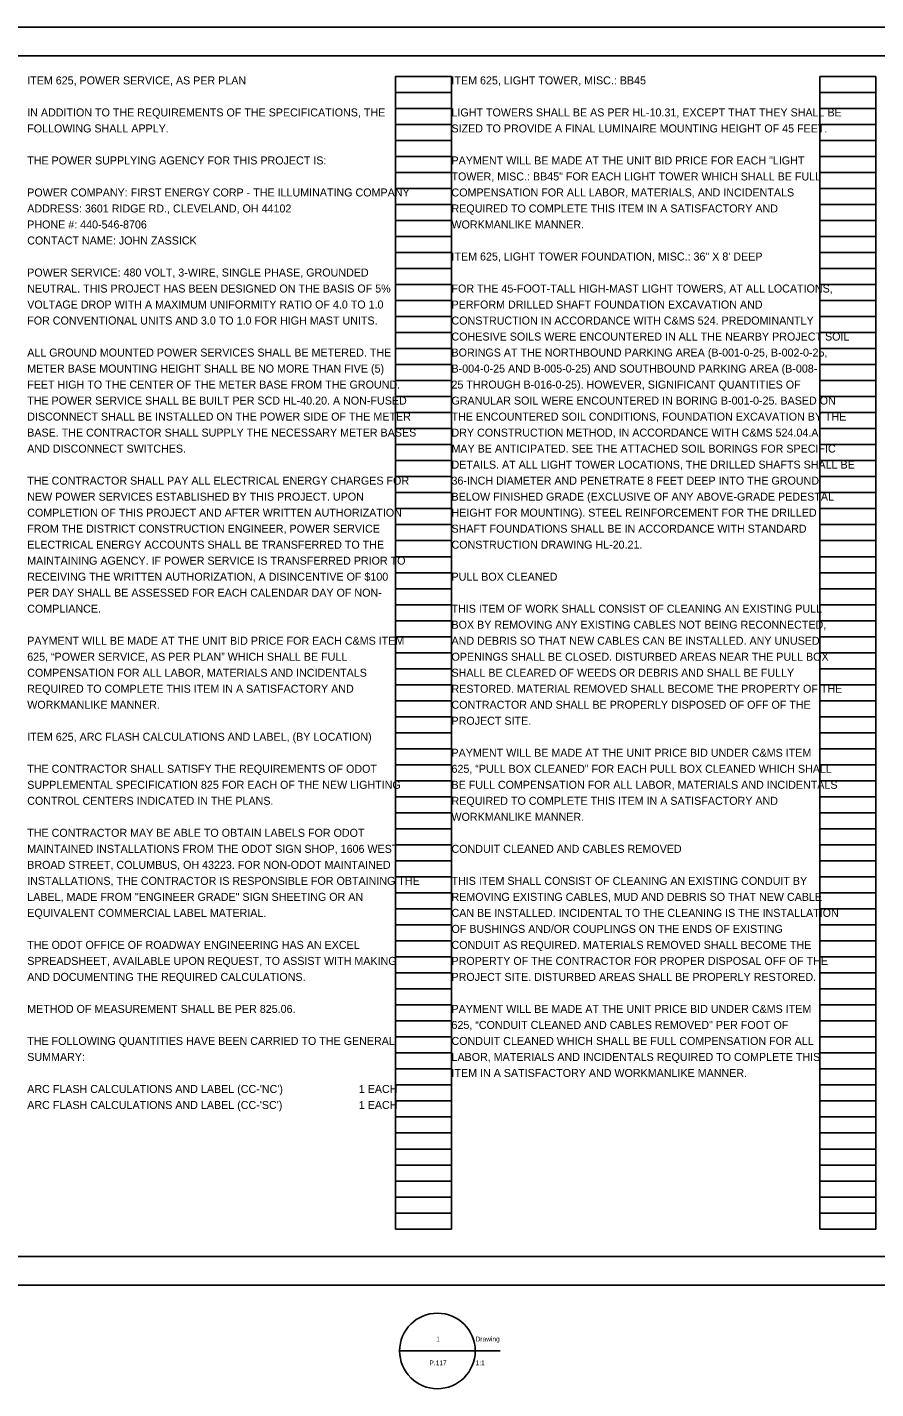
# Model space of a CAD drawing. Extents: x 0 to 49.8, y -1.8 to 22.
# Drawn here: x 9.82 to 24.66, y -1.81 to 22 of the extents above; entities that cross this region are included whole.
import ezdxf

# ---------------------------------------------------------------- set-up
doc = ezdxf.new("R2010")
doc.units = 0
for name, color, linetype in [('SH_Border', 7, 'Continuous'), ('SH_Cut_Line', 7, 'Continuous'), ('SH_Data', 7, 'Continuous'), ('SH_Text', 7, 'Continuous')]:
    doc.layers.add(name, color=color, linetype=linetype)

msp = doc.modelspace()

# ---------------------------------------------------------------- linework, layer by layer
at = {"layer": 'SH_Border'}
msp.add_lwpolyline([(1.5, 21.5), (33.5, 21.5), (33.5, 0.5), (1.5, 0.5)], close=True, dxfattribs=at)
at = {"layer": 'SH_Cut_Line'}
msp.add_lwpolyline([(0, 0), (34, 0), (34, 22), (0, 22)], close=True, dxfattribs=at)
at = {"layer": 'SH_Data'}
for p, q in [((16.26, 0.98), (16.26, 21.14)), ((16.26, 21.14), (17.24, 21.14)), ((17.24, 0.98), (17.24, 21.14)), ((23.68, 0.98), (23.68, 21.14)), ((23.68, 21.14), (24.66, 21.14)), ((24.66, 0.98), (24.66, 21.14)), ((16.26, 20.86), (17.24, 20.86)), ((23.68, 20.86), (24.66, 20.86)), ((16.26, 20.58), (17.24, 20.58)), ((23.68, 20.58), (24.66, 20.58)), ((16.26, 20.3), (17.24, 20.3)), ((23.68, 20.3), (24.66, 20.3)), ((16.26, 20.02), (17.24, 20.02)), ((23.68, 20.02), (24.66, 20.02)), ((16.26, 19.74), (17.24, 19.74)), ((23.68, 19.74), (24.66, 19.74)), ((16.26, 19.46), (17.24, 19.46)), ((23.68, 19.46), (24.66, 19.46)), ((16.26, 19.18), (17.24, 19.18)), ((23.68, 19.18), (24.66, 19.18)), ((16.26, 18.9), (17.24, 18.9)), ((23.68, 18.9), (24.66, 18.9)), ((16.26, 18.62), (17.24, 18.62)), ((23.68, 18.62), (24.66, 18.62)), ((16.26, 18.34), (17.24, 18.34)), ((23.68, 18.34), (24.66, 18.34)), ((16.26, 18.06), (17.24, 18.06)), ((23.68, 18.06), (24.66, 18.06)), ((16.26, 17.78), (17.24, 17.78)), ((23.68, 17.78), (24.66, 17.78)), ((16.26, 17.5), (17.24, 17.5)), ((23.68, 17.5), (24.66, 17.5)), ((16.26, 17.22), (17.24, 17.22)), ((23.68, 17.22), (24.66, 17.22)), ((16.26, 16.94), (17.24, 16.94)), ((23.68, 16.94), (24.66, 16.94)), ((16.26, 16.66), (17.24, 16.66)), ((23.68, 16.66), (24.66, 16.66)), ((16.26, 16.38), (17.24, 16.38)), ((23.68, 16.38), (24.66, 16.38)), ((16.26, 16.1), (17.24, 16.1)), ((23.68, 16.1), (24.66, 16.1)), ((16.26, 15.82), (17.24, 15.82)), ((23.68, 15.82), (24.66, 15.82)), ((16.26, 15.54), (17.24, 15.54)), ((23.68, 15.54), (24.66, 15.54)), ((16.26, 15.26), (17.24, 15.26)), ((23.68, 15.26), (24.66, 15.26)), ((16.26, 14.98), (17.24, 14.98)), ((23.68, 14.98), (24.66, 14.98)), ((16.26, 14.7), (17.24, 14.7)), ((23.68, 14.7), (24.66, 14.7)), ((16.26, 14.42), (17.24, 14.42)), ((23.68, 14.42), (24.66, 14.42)), ((16.26, 14.14), (17.24, 14.14)), ((23.68, 14.14), (24.66, 14.14)), ((16.26, 13.86), (17.24, 13.86)), ((23.68, 13.86), (24.66, 13.86)), ((16.26, 13.58), (17.24, 13.58)), ((23.68, 13.58), (24.66, 13.58)), ((16.26, 13.3), (17.24, 13.3)), ((23.68, 13.3), (24.66, 13.3)), ((16.26, 13.02), (17.24, 13.02)), ((23.68, 13.02), (24.66, 13.02)), ((16.26, 12.74), (17.24, 12.74)), ((23.68, 12.74), (24.66, 12.74)), ((16.26, 12.46), (17.24, 12.46)), ((23.68, 12.46), (24.66, 12.46)), ((16.26, 12.18), (17.24, 12.18)), ((23.68, 12.18), (24.66, 12.18)), ((16.26, 11.9), (17.24, 11.9)), ((23.68, 11.9), (24.66, 11.9)), ((16.26, 11.62), (17.24, 11.62)), ((23.68, 11.62), (24.66, 11.62)), ((16.26, 11.34), (17.24, 11.34)), ((23.68, 11.34), (24.66, 11.34)), ((16.26, 11.06), (17.24, 11.06)), ((23.68, 11.06), (24.66, 11.06)), ((16.26, 10.78), (17.24, 10.78)), ((23.68, 10.78), (24.66, 10.78)), ((16.26, 10.5), (17.24, 10.5)), ((23.68, 10.5), (24.66, 10.5)), ((16.26, 10.22), (17.24, 10.22)), ((23.68, 10.22), (24.66, 10.22)), ((16.26, 9.94), (17.24, 9.94)), ((23.68, 9.94), (24.66, 9.94)), ((16.26, 9.66), (17.24, 9.66)), ((23.68, 9.66), (24.66, 9.66)), ((16.26, 9.38), (17.24, 9.38)), ((23.68, 9.38), (24.66, 9.38)), ((16.26, 9.1), (17.24, 9.1)), ((23.68, 9.1), (24.66, 9.1)), ((16.26, 8.82), (17.24, 8.82)), ((23.68, 8.82), (24.66, 8.82)), ((16.26, 8.54), (17.24, 8.54)), ((23.68, 8.54), (24.66, 8.54)), ((16.26, 8.26), (17.24, 8.26)), ((23.68, 8.26), (24.66, 8.26)), ((16.26, 7.98), (17.24, 7.98)), ((23.68, 7.98), (24.66, 7.98)), ((16.26, 7.7), (17.24, 7.7)), ((23.68, 7.7), (24.66, 7.7)), ((16.26, 7.42), (17.24, 7.42)), ((23.68, 7.42), (24.66, 7.42)), ((16.26, 7.14), (17.24, 7.14)), ((23.68, 7.14), (24.66, 7.14)), ((16.26, 6.86), (17.24, 6.86)), ((23.68, 6.86), (24.66, 6.86)), ((16.26, 6.58), (17.24, 6.58)), ((23.68, 6.58), (24.66, 6.58)), ((16.26, 6.3), (17.24, 6.3)), ((23.68, 6.3), (24.66, 6.3)), ((16.26, 6.02), (17.24, 6.02)), ((23.68, 6.02), (24.66, 6.02)), ((16.26, 5.74), (17.24, 5.74)), ((23.68, 5.74), (24.66, 5.74)), ((16.26, 5.46), (17.24, 5.46)), ((23.68, 5.46), (24.66, 5.46)), ((16.26, 5.18), (17.24, 5.18)), ((23.68, 5.18), (24.66, 5.18)), ((16.26, 4.9), (17.24, 4.9)), ((23.68, 4.9), (24.66, 4.9)), ((16.26, 4.62), (17.24, 4.62)), ((23.68, 4.62), (24.66, 4.62)), ((16.26, 4.34), (17.24, 4.34)), ((23.68, 4.34), (24.66, 4.34)), ((16.26, 4.06), (17.24, 4.06)), ((23.68, 4.06), (24.66, 4.06)), ((16.26, 3.78), (17.24, 3.78)), ((23.68, 3.78), (24.66, 3.78)), ((16.26, 3.5), (17.24, 3.5)), ((23.68, 3.5), (24.66, 3.5)), ((16.26, 3.22), (17.24, 3.22)), ((23.68, 3.22), (24.66, 3.22)), ((16.26, 2.94), (17.24, 2.94)), ((23.68, 2.94), (24.66, 2.94)), ((16.26, 2.66), (17.24, 2.66)), ((23.68, 2.66), (24.66, 2.66)), ((16.26, 2.38), (17.24, 2.38)), ((23.68, 2.38), (24.66, 2.38)), ((16.26, 2.1), (17.24, 2.1)), ((23.68, 2.1), (24.66, 2.1)), ((16.26, 1.82), (17.24, 1.82)), ((23.68, 1.82), (24.66, 1.82)), ((16.26, 1.54), (17.24, 1.54)), ((23.68, 1.54), (24.66, 1.54)), ((16.26, 1.26), (17.24, 1.26)), ((23.68, 1.26), (24.66, 1.26)), ((16.26, 0.98), (17.24, 0.98)), ((23.68, 0.98), (24.66, 0.98))]:
    msp.add_line(p, q, dxfattribs=at)
at = {"layer": 'SH_Text'}
for p, q in [((16.333, -1.152), (17.656, -1.152)), ((17, -1.152), (18.09, -1.152))]:
    msp.add_line(p, q, dxfattribs=at)
msp.add_circle((16.994, -1.152), 0.661, dxfattribs=at)

# ---------------------------------------------------------------- texts
for s, height, p in [('ITEM 625, POWER SERVICE, AS PER PLAN', 0.14, (9.82, 21)), ('ITEM 625, LIGHT TOWER, MISC.: BB45', 0.14, (17.24, 21)), ('IN ADDITION TO THE REQUIREMENTS OF THE SPECIFICATIONS, THE ', 0.14, (9.82, 20.44)), ('LIGHT TOWERS SHALL BE AS PER HL-10.31, EXCEPT THAT THEY SHALL BE ', 0.14, (17.24, 20.44)), ('FOLLOWING SHALL APPLY.', 0.14, (9.82, 20.16)), ('SIZED TO PROVIDE A FINAL LUMINAIRE MOUNTING HEIGHT OF 45 FEET.', 0.14, (17.24, 20.16)), ('THE POWER SUPPLYING AGENCY FOR THIS PROJECT IS:', 0.14, (9.82, 19.6)), ('PAYMENT WILL BE MADE AT THE UNIT BID PRICE FOR EACH "LIGHT ', 0.14, (17.24, 19.6)), ('TOWER, MISC.: BB45" FOR EACH LIGHT TOWER WHICH SHALL BE FULL ', 0.14, (17.24, 19.32)), ('POWER COMPANY: FIRST ENERGY CORP - THE ILLUMINATING COMPANY', 0.14, (9.82, 19.04)), ('COMPENSATION FOR ALL LABOR, MATERIALS, AND INCIDENTALS ', 0.14, (17.24, 19.04)), ('ADDRESS: 3601 RIDGE RD., CLEVELAND, OH 44102', 0.14, (9.82, 18.76)), ('REQUIRED TO COMPLETE THIS ITEM IN A SATISFACTORY AND ', 0.14, (17.24, 18.76)), ('PHONE #: 440-546-8706', 0.14, (9.82, 18.48)), ('WORKMANLIKE MANNER.', 0.14, (17.24, 18.48)), ('CONTACT NAME: JOHN ZASSICK', 0.14, (9.82, 18.2)), ('ITEM 625, LIGHT TOWER FOUNDATION, MISC.: 36" X 8\' DEEP', 0.14, (17.24, 17.92)), ('POWER SERVICE: 480 VOLT, 3-WIRE, SINGLE PHASE, GROUNDED ', 0.14, (9.82, 17.64)), ('NEUTRAL. THIS PROJECT HAS BEEN DESIGNED ON THE BASIS OF 5% ', 0.14, (9.82, 17.36)), ('FOR THE 45-FOOT-TALL HIGH-MAST LIGHT TOWERS, AT ALL LOCATIONS, ', 0.14, (17.24, 17.36)), ('VOLTAGE DROP WITH A MAXIMUM UNIFORMITY RATIO OF 4.0 TO 1.0 ', 0.14, (9.82, 17.08)), ('PERFORM DRILLED SHAFT FOUNDATION EXCAVATION AND ', 0.14, (17.24, 17.08)), ('FOR CONVENTIONAL UNITS AND 3.0 TO 1.0 FOR HIGH MAST UNITS.', 0.14, (9.82, 16.8)), ('CONSTRUCTION IN ACCORDANCE WITH C&MS 524. PREDOMINANTLY ', 0.14, (17.24, 16.8)), ('COHESIVE SOILS WERE ENCOUNTERED IN ALL THE NEARBY PROJECT SOIL ', 0.14, (17.24, 16.52)), ('ALL GROUND MOUNTED POWER SERVICES SHALL BE METERED. THE ', 0.14, (9.82, 16.24)), ('BORINGS AT THE NORTHBOUND PARKING AREA (B-001-0-25, B-002-0-25, ', 0.14, (17.24, 16.24)), ('METER BASE MOUNTING HEIGHT SHALL BE NO MORE THAN FIVE (5) ', 0.14, (9.82, 15.96)), ('B-004-0-25 AND B-005-0-25) AND SOUTHBOUND PARKING AREA (B-008-', 0.14, (17.24, 15.96)), ('FEET HIGH TO THE CENTER OF THE METER BASE FROM THE GROUND. ', 0.14, (9.82, 15.68)), ('25 THROUGH B-016-0-25). HOWEVER, SIGNIFICANT QUANTITIES OF ', 0.14, (17.24, 15.68)), ('THE POWER SERVICE SHALL BE BUILT PER SCD HL-40.20. A NON-FUSED ', 0.14, (9.82, 15.4)), ('GRANULAR SOIL WERE ENCOUNTERED IN BORING B-001-0-25. BASED ON ', 0.14, (17.24, 15.4)), ('DISCONNECT SHALL BE INSTALLED ON THE POWER SIDE OF THE METER ', 0.14, (9.82, 15.12)), ('THE ENCOUNTERED SOIL CONDITIONS, FOUNDATION EXCAVATION BY THE ', 0.14, (17.24, 15.12)), ('BASE. THE CONTRACTOR SHALL SUPPLY THE NECESSARY METER BASES ', 0.14, (9.82, 14.84)), ('DRY CONSTRUCTION METHOD, IN ACCORDANCE WITH C&MS 524.04.A, ', 0.14, (17.24, 14.84)), ('AND DISCONNECT SWITCHES.', 0.14, (9.82, 14.56)), ('MAY BE ANTICIPATED. SEE THE ATTACHED SOIL BORINGS FOR SPECIFIC ', 0.14, (17.24, 14.56)), ('DETAILS. AT ALL LIGHT TOWER LOCATIONS, THE DRILLED SHAFTS SHALL BE ', 0.14, (17.24, 14.28)), ('THE CONTRACTOR SHALL PAY ALL ELECTRICAL ENERGY CHARGES FOR ', 0.14, (9.82, 14)), ('36-INCH DIAMETER AND PENETRATE 8 FEET DEEP INTO THE GROUND ', 0.14, (17.24, 14)), ('NEW POWER SERVICES ESTABLISHED BY THIS PROJECT. UPON ', 0.14, (9.82, 13.72)), ('BELOW FINISHED GRADE (EXCLUSIVE OF ANY ABOVE-GRADE PEDESTAL ', 0.14, (17.24, 13.72)), ('COMPLETION OF THIS PROJECT AND AFTER WRITTEN AUTHORIZATION ', 0.14, (9.82, 13.44)), ('HEIGHT FOR MOUNTING). STEEL REINFORCEMENT FOR THE DRILLED ', 0.14, (17.24, 13.44)), ('FROM THE DISTRICT CONSTRUCTION ENGINEER, POWER SERVICE ', 0.14, (9.82, 13.16)), ('SHAFT FOUNDATIONS SHALL BE IN ACCORDANCE WITH STANDARD ', 0.14, (17.24, 13.16)), ('ELECTRICAL ENERGY ACCOUNTS SHALL BE TRANSFERRED TO THE ', 0.14, (9.82, 12.88)), ('CONSTRUCTION DRAWING HL-20.21.', 0.14, (17.24, 12.88)), ('MAINTAINING AGENCY. IF POWER SERVICE IS TRANSFERRED PRIOR TO ', 0.14, (9.82, 12.6)), ('RECEIVING THE WRITTEN AUTHORIZATION, A DISINCENTIVE OF $100 ', 0.14, (9.82, 12.32)), ('PULL BOX CLEANED', 0.14, (17.24, 12.32)), ('PER DAY SHALL BE ASSESSED FOR EACH CALENDAR DAY OF NON-', 0.14, (9.82, 12.04)), ('COMPLIANCE.', 0.14, (9.82, 11.76)), ('THIS ITEM OF WORK SHALL CONSIST OF CLEANING AN EXISTING PULL ', 0.14, (17.24, 11.76)), ('BOX BY REMOVING ANY EXISTING CABLES NOT BEING RECONNECTED, ', 0.14, (17.24, 11.48)), ('PAYMENT WILL BE MADE AT THE UNIT BID PRICE FOR EACH C&MS ITEM ', 0.14, (9.82, 11.2)), ('AND DEBRIS SO THAT NEW CABLES CAN BE INSTALLED. ANY UNUSED ', 0.14, (17.24, 11.2)), ('625, “POWER SERVICE, AS PER PLAN” WHICH SHALL BE FULL ', 0.14, (9.82, 10.92)), ('OPENINGS SHALL BE CLOSED. DISTURBED AREAS NEAR THE PULL BOX ', 0.14, (17.24, 10.92)), ('COMPENSATION FOR ALL LABOR, MATERIALS AND INCIDENTALS ', 0.14, (9.82, 10.64)), ('SHALL BE CLEARED OF WEEDS OR DEBRIS AND SHALL BE FULLY ', 0.14, (17.24, 10.64)), ('REQUIRED TO COMPLETE THIS ITEM IN A SATISFACTORY AND ', 0.14, (9.82, 10.36)), ('RESTORED. MATERIAL REMOVED SHALL BECOME THE PROPERTY OF THE ', 0.14, (17.24, 10.36)), ('WORKMANLIKE MANNER.', 0.14, (9.82, 10.08)), ('CONTRACTOR AND SHALL BE PROPERLY DISPOSED OF OFF OF THE ', 0.14, (17.24, 10.08)), ('PROJECT SITE.', 0.14, (17.24, 9.8)), ('ITEM 625, ARC FLASH CALCULATIONS AND LABEL, (BY LOCATION)', 0.14, (9.82, 9.52)), ('PAYMENT WILL BE MADE AT THE UNIT PRICE BID UNDER C&MS ITEM ', 0.14, (17.24, 9.24)), ('THE CONTRACTOR SHALL SATISFY THE REQUIREMENTS OF ODOT ', 0.14, (9.82, 8.96)), ('625, “PULL BOX CLEANED" FOR EACH PULL BOX CLEANED WHICH SHALL ', 0.14, (17.24, 8.96)), ('SUPPLEMENTAL SPECIFICATION 825 FOR EACH OF THE NEW LIGHTING ', 0.14, (9.82, 8.68)), ('BE FULL COMPENSATION FOR ALL LABOR, MATERIALS AND INCIDENTALS ', 0.14, (17.24, 8.68)), ('CONTROL CENTERS INDICATED IN THE PLANS.', 0.14, (9.82, 8.4)), ('REQUIRED TO COMPLETE THIS ITEM IN A SATISFACTORY AND ', 0.14, (17.24, 8.4)), ('WORKMANLIKE MANNER.', 0.14, (17.24, 8.12)), ('THE CONTRACTOR MAY BE ABLE TO OBTAIN LABELS FOR ODOT ', 0.14, (9.82, 7.84)), ('MAINTAINED INSTALLATIONS FROM THE ODOT SIGN SHOP, 1606 WEST ', 0.14, (9.82, 7.56)), ('CONDUIT CLEANED AND CABLES REMOVED', 0.14, (17.24, 7.56)), ('BROAD STREET, COLUMBUS, OH 43223. FOR NON-ODOT MAINTAINED ', 0.14, (9.82, 7.28)), ('INSTALLATIONS, THE CONTRACTOR IS RESPONSIBLE FOR OBTAINING THE ', 0.14, (9.82, 7)), ('THIS ITEM SHALL CONSIST OF CLEANING AN EXISTING CONDUIT BY ', 0.14, (17.24, 7)), ('LABEL, MADE FROM "ENGINEER GRADE" SIGN SHEETING OR AN ', 0.14, (9.82, 6.72)), ('REMOVING EXISTING CABLES, MUD AND DEBRIS SO THAT NEW CABLE ', 0.14, (17.24, 6.72)), ('EQUIVALENT COMMERCIAL LABEL MATERIAL.', 0.14, (9.82, 6.44)), ('CAN BE INSTALLED. INCIDENTAL TO THE CLEANING IS THE INSTALLATION ', 0.14, (17.24, 6.44)), ('OF BUSHINGS AND/OR COUPLINGS ON THE ENDS OF EXISTING ', 0.14, (17.24, 6.16)), ('THE ODOT OFFICE OF ROADWAY ENGINEERING HAS AN EXCEL ', 0.14, (9.82, 5.88)), ('CONDUIT AS REQUIRED. MATERIALS REMOVED SHALL BECOME THE ', 0.14, (17.24, 5.88)), ('SPREADSHEET, AVAILABLE UPON REQUEST, TO ASSIST WITH MAKING ', 0.14, (9.82, 5.6)), ('PROPERTY OF THE CONTRACTOR FOR PROPER DISPOSAL OFF OF THE ', 0.14, (17.24, 5.6)), ('AND DOCUMENTING THE REQUIRED CALCULATIONS.', 0.14, (9.82, 5.32)), ('PROJECT SITE. DISTURBED AREAS SHALL BE PROPERLY RESTORED.', 0.14, (17.24, 5.32)), ('METHOD OF MEASUREMENT SHALL BE PER 825.06.', 0.14, (9.82, 4.76)), ('PAYMENT WILL BE MADE AT THE UNIT PRICE BID UNDER C&MS ITEM ', 0.14, (17.24, 4.76)), ('625, “CONDUIT CLEANED AND CABLES REMOVED" PER FOOT OF ', 0.14, (17.24, 4.48)), ('THE FOLLOWING QUANTITIES HAVE BEEN CARRIED TO THE GENERAL ', 0.14, (9.82, 4.2)), ('CONDUIT CLEANED WHICH SHALL BE FULL COMPENSATION FOR ALL ', 0.14, (17.24, 4.2)), ('SUMMARY:', 0.14, (9.82, 3.92)), ('LABOR, MATERIALS AND INCIDENTALS REQUIRED TO COMPLETE THIS ', 0.14, (17.24, 3.92)), ('ITEM IN A SATISFACTORY AND WORKMANLIKE MANNER.', 0.14, (17.24, 3.64)), ("ARC FLASH CALCULATIONS AND LABEL (CC-'NC')", 0.14, (9.82, 3.36)), ('1 EACH', 0.14, (15.619, 3.36)), ("ARC FLASH CALCULATIONS AND LABEL (CC-'SC')", 0.14, (9.82, 3.08)), ('1 EACH', 0.14, (15.619, 3.08)), ('1', 0.0833, (16.973, -0.985)), ('Drawing', 0.0833, (17.662, -0.985)), ('P.117', 0.0833, (16.855, -1.402)), ('1:1', 0.0833, (17.662, -1.402))]:
    msp.add_text(s, height=height, dxfattribs=at).set_placement(p)

doc.saveas('drawing.dxf')
